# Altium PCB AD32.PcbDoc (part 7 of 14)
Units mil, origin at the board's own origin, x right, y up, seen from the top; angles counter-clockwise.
Board outline 7007.87 x 4368.85 mil, 12 copper layers (Top Layer, Int1 (GND), Int2 (AVDD), Int3 (DVDD), Int4 (GND), Int5 (ST), Int6 (SB), Int8 (AGND), Int7 (AVCC), Int9 (VCCA), Int10 (GND), Bottom Layer), stack 60.136 mil thick; 1350 components, 880 nets, 4712 pads, 2835 vias.
Unrouted connection lines stored in the file: 19.
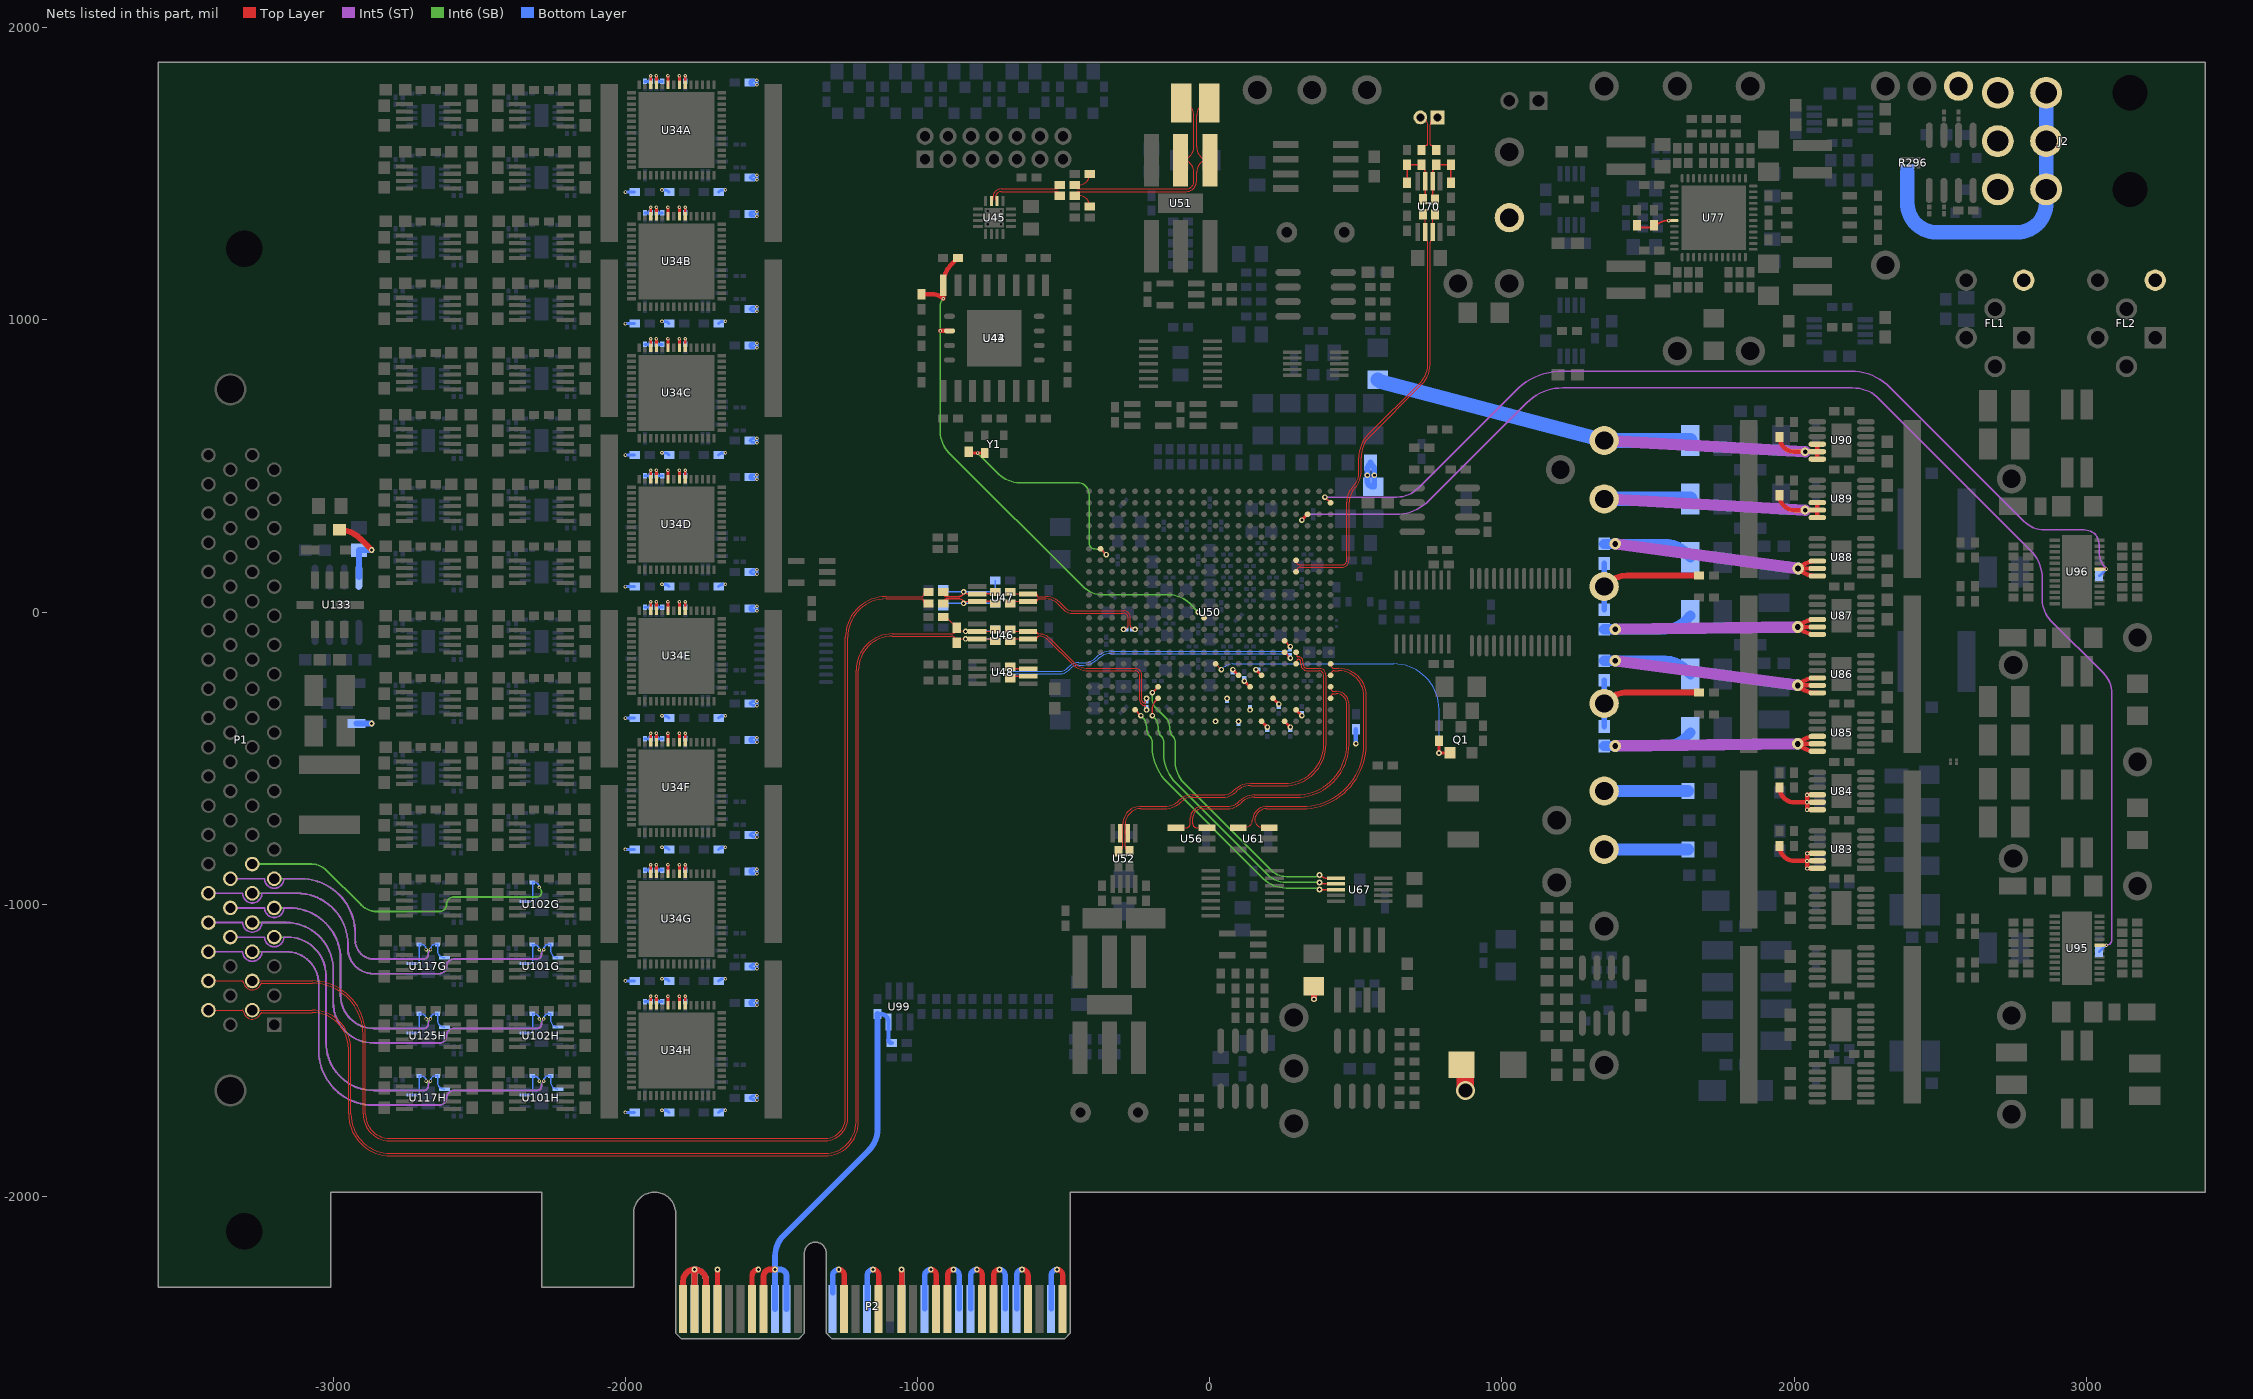
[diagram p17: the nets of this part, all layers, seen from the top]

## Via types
v1: diameter 12, hole 6, Top Layer to Bottom Layer, tented both sides, 1497 vias
v2: diameter 20, hole 10, Top Layer to Bottom Layer, tented both sides, 364 vias
v3: diameter 19, hole 10, Top Layer to Bottom Layer, tented both sides, 347 vias
v4: diameter 14, hole 7, Top Layer to Bottom Layer, tented both sides, 228 vias
v5: diameter 19.68, hole 7.87, Top Layer to Bottom Layer, 225 vias
v6: diameter 19.02, hole 10, Top Layer to Bottom Layer, tented both sides, 85 vias
v7: diameter 20, hole 10, Top Layer to Bottom Layer, 32 vias
v8: diameter 40, hole 20, Top Layer to Bottom Layer, tented both sides, 14 vias
v9: diameter 30, hole 15, Top Layer to Bottom Layer, tented both sides, 12 vias
v10: diameter 25, hole 13, Top Layer to Bottom Layer, 8 vias
v11: diameter 40, hole 20, Top Layer to Bottom Layer, 6 vias
v12: diameter 50, hole 20, Top Layer to Bottom Layer, 6 vias
v13: diameter 66, hole 47, Top Layer to Bottom Layer, tented both sides, 3 vias
v14: diameter 63, hole 45, Top Layer to Bottom Layer, 2 vias
v15: diameter 50, hole 25, Top Layer to Bottom Layer, 2 vias
v16: diameter 12, hole 6, Top Layer to Bottom Layer, 2 vias
v17: diameter 60, hole 40, Top Layer to Bottom Layer, tented both sides, 1 vias
v18: diameter 60, hole 40, Top Layer to Bottom Layer, 1 vias

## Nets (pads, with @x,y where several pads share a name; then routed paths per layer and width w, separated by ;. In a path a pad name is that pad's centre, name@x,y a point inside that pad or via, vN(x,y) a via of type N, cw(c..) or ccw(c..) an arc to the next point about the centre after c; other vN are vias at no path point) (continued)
ANALOG4.A2_P: P1.23 R569G.2 U102G.3 | length 1230.2
  Int6 (SB) w6: P1.23@-3277.3,-862.5 -3074.1,-862.5 cw(c-3074.1,-933.71) -3023.74,-883.36 -2904.8,-1002.3 ccw(c-2850,-947.5) -2850,-1025 -2637.37,-1025 ccw(c-2637.37,-1000.13) -2612.5,-1000.13 -2612.5,-1000 cw(c-2587.5,-1000) -2587.5,-975 -2302.5,-975 ccw(c-2302.5,-960) -2287.5,-960 ccw(c-2311.64,-960) -2294.57,-942.93 v1(-2295,-942.5)
  Bottom Layer w5: U102G.3@-2343.6,-990.16 -2326.41,-990.16 ccw(c-2326.41,-981.25) -2317.5,-981.25 -2317.5,-926.81 ccw(c-2319.31,-926.81) R569G.2@-2319.31,-925 -2312.5,-925 cw(c-2312.5,-942.5) v1(-2295,-942.5)
ANALOG4.A3_N: P1.22 R617G.1 U117G.5 | length 1003.8
  Int5 (ST) w6: P1.22@-3352.3,-912.5 -3235.3,-912.5 ccw(c-3202.3,-912.5) -3169.3,-912.5 -3159.09,-912.5 -3112.33,-912.5 cw(c-3112.33,-1099.83) -2925,-1099.83 -2925,-1123.44 ccw(c-2860.94,-1123.44) -2860.94,-1187.5 -2690,-1187.5 ccw(c-2690,-1172.5) -2675,-1172.5 cw(c-2650.86,-1172.5) -2667.93,-1155.43 v1(-2667.5,-1155)
  Bottom Layer w5: v1(-2667.5,-1155) cw(c-2650,-1155) -2650,-1137.5 R617G.1@-2643.19,-1137.5 -2643.19,-1158.68 ccw(c-2618.89,-1158.68) U117G.5@-2618.89,-1182.97
ANALOG4.A3_P: P1.21 R633G.2 U117G.3 | length 844.8
  Int6 (SB) w6: P1.21@-3202.3,-912.5 -3112.33,-912.5 cw(c-3112.33,-1099.83) -2925,-1099.83 -2925,-1123.44 ccw(c-2860.94,-1123.44) -2860.94,-1187.5 -2690,-1187.5 ccw(c-2690,-1172.5) -2675,-1172.5 ccw(c-2699.14,-1172.5) -2682.07,-1155.43 v1(-2682.5,-1155)
  Bottom Layer w5: U117G.3@-2731.1,-1202.66 -2713.91,-1202.66 ccw(c-2713.91,-1193.75) -2705,-1193.75 -2705,-1141.88 ccw(c-2711.19,-1141.88) R633G.2@-2706.81,-1137.5 -2700,-1137.5 cw(c-2700,-1155) v1(-2682.5,-1155)
ANALOG4.A4_N: P1.20 R553G.1 U101G.5 | length 1490.4
  Int5 (ST) w6: P1.20@-3427.3,-962.5 -3310.3,-962.5 ccw(c-3277.3,-962.5) -3244.3,-962.5 -3124.63,-962.5 cw(c-3124.63,-1137.13) -2950,-1137.13 -2950,-1150.27 ccw(c-2862.77,-1150.27) -2862.77,-1237.5 -2637.5,-1237.5 ccw(c-2637.5,-1212.5) -2612.5,-1212.5 cw(c-2587.5,-1212.5) -2587.5,-1187.5 -2302.5,-1187.5 ccw(c-2302.5,-1172.5) -2287.5,-1172.5 cw(c-2263.36,-1172.5) -2280.43,-1155.43 v1(-2280,-1155)
  Bottom Layer w5: v1(-2280,-1155) cw(c-2262.5,-1155) -2262.5,-1137.5 R553G.1@-2255.69,-1137.5 -2255.69,-1158.68 ccw(c-2231.39,-1158.68) U101G.5@-2231.39,-1182.97
ANALOG4.A4_P: P1.19 R577G.2 U101G.3 | length 1329
  Int6 (SB) w6: P1.19@-3277.3,-962.5 -3124.63,-962.5 cw(c-3124.63,-1137.13) -2950,-1137.13 -2950,-1150.27 ccw(c-2862.77,-1150.27) -2862.77,-1237.5 -2637.5,-1237.5 ccw(c-2637.5,-1212.5) -2612.5,-1212.5 cw(c-2587.5,-1212.5) -2587.5,-1187.5 -2302.5,-1187.5 ccw(c-2302.5,-1172.5) -2287.5,-1172.5 ccw(c-2311.64,-1172.5) -2294.57,-1155.43 v1(-2295,-1155)
  Bottom Layer w5: U101G.3@-2343.6,-1202.66 -2326.41,-1202.66 ccw(c-2326.41,-1193.75) -2317.5,-1193.75 R577G.2@-2317.5,-1139.41 ; R577G.2@-2319.41,-1137.5 cw(c-2319.41,-1139.41) R577G.2@-2317.5,-1139.41 ; v1(-2295,-1155) ccw(c-2310.59,-1155) -2310.59,-1139.41 R577G.2@-2317.5,-1139.41
ANALOG4.A5_N: P1.18 R618H.1 U125H.5 | length 1123.5
  Int5 (ST) w6: P1.18@-3352.3,-1012.5 -3235.3,-1012.5 ccw(c-3202.3,-1012.5) -3169.3,-1012.5 ; -3167.5,-1012.5 -3151.36,-1012.5 cw(c-3151.36,-1188.86) -2975,-1188.86 -2975,-1312.26 ccw(c-2862.26,-1312.26) -2862.26,-1425 -2690,-1425 ccw(c-2690,-1410) -2675,-1410 cw(c-2650.86,-1410) -2667.93,-1392.93 v1(-2667.5,-1392.5)
  Bottom Layer w5: v1(-2667.5,-1392.5) cw(c-2650,-1392.5) -2650,-1375 R618H.1@-2643.19,-1375 -2643.19,-1396.31 ccw(c-2618.89,-1396.31) U125H.5@-2618.89,-1420.6
ANALOG4.A5_P: P1.17 R634H.2 U125H.3 | length 966.7
  Int6 (SB) w6: P1.17@-3202.3,-1012.5 -3151.36,-1012.5 cw(c-3151.36,-1188.86) -2975,-1188.86 -2975,-1312.26 ccw(c-2862.26,-1312.26) -2862.26,-1425 -2690,-1425 ccw(c-2690,-1410) -2675,-1410 ccw(c-2699.14,-1410) -2682.07,-1392.93 v1(-2682.5,-1392.5)
  Bottom Layer w5: U125H.3@-2731.1,-1440.28 -2714.03,-1440.28 ccw(c-2714.03,-1431.25) -2705,-1431.25 -2705,-1376.81 ccw(c-2706.81,-1376.81) R634H.2@-2706.81,-1375 -2700,-1375 cw(c-2700,-1392.5) v1(-2682.5,-1392.5)
ANALOG4.A6_N: P1.16 R554H.1 U102H.5 | length 1611.6
  Int5 (ST) w6: P1.16@-3427.3,-1062.5 -3310.3,-1062.5 ccw(c-3277.3,-1062.5) -3244.3,-1062.5 -3174.68,-1062.5 cw(c-3163.29,-1225.39) -3000,-1225.39 ; -3000,-1225.03 -3000,-1225.39 ; v1(-2280,-1392.5) -2280.43,-1392.93 ccw(c-2263.36,-1410) -2287.5,-1410 cw(c-2302.5,-1410) -2302.5,-1425 -2587.5,-1425 ccw(c-2587.5,-1450) -2612.5,-1450 cw(c-2637.5,-1450) -2637.5,-1475 -2861.78,-1475 cw(c-2861.78,-1336.78) -3000,-1336.78 -3000,-1225.39
  Bottom Layer w5: v1(-2280,-1392.5) cw(c-2262.5,-1392.5) -2262.5,-1375 R554H.1@-2255.69,-1375 -2255.69,-1396.18 ccw(c-2231.39,-1396.18) U102H.5@-2231.39,-1420.47
ANALOG4.A6_P: P1.15 R569H.2 U102H.3 | length 1453.2
  Int6 (SB) w6: P1.15@-3277.3,-1062.5 -3162.53,-1062.5 cw(c-3162.53,-1225.03) -3000,-1225.03 ; -3000,-1225.3 -3000,-1336.78 ccw(c-2861.78,-1336.78) -2862.5,-1475 ; v1(-2295,-1392.5) -2294.57,-1392.93 cw(c-2311.64,-1410) -2287.5,-1410 cw(c-2302.5,-1410) -2302.5,-1425 -2587.5,-1425 ccw(c-2587.5,-1450) -2612.5,-1450 -2612.5,-1450.13 cw(c-2637.37,-1450.13) -2637.37,-1475 -2861.78,-1475 ; -2862.5,-1475 ccw(c-2861.78,-1336.78) -2861.78,-1475 ; -2862.5,-1475 -2861.78,-1475
  Bottom Layer w5: U102H.3@-2343.6,-1440.16 -2326.41,-1440.16 ccw(c-2326.41,-1431.25) -2317.5,-1431.25 -2317.5,-1376.81 ccw(c-2319.31,-1376.81) R569H.2@-2319.31,-1375 -2312.5,-1375 cw(c-2312.5,-1392.5) v1(-2295,-1392.5)
ANALOG4.A7_N: P1.14 R617H.1 U117H.5 | length 1235.1
  Int5 (ST) w6: P1.14@-3352.3,-1112.5 -3235.3,-1112.5 ccw(c-3202.3,-1112.5) -3169.3,-1112.5 -3156.11,-1112.5 cw(c-3156.11,-1243.61) -3025,-1243.61 -3025,-1473.44 ccw(c-2860.94,-1473.44) -2860.94,-1637.5 -2690,-1637.5 ccw(c-2690,-1622.5) -2675,-1622.5 cw(c-2650.86,-1622.5) -2667.93,-1605.43 v1(-2667.5,-1605)
  Bottom Layer w5: v1(-2667.5,-1605) cw(c-2650,-1605) -2650,-1587.5 R617H.1@-2643.19,-1587.5 -2643.19,-1608.68 ccw(c-2618.89,-1608.68) U117H.5@-2618.89,-1632.97
ANALOG4.A7_P: P1.13 R633H.2 U117H.3 | length 1075.6
  Int6 (SB) w6: P1.13@-3202.3,-1112.5 -3156.97,-1112.5 cw(c-3156.97,-1244.47) -3025,-1244.47 -3025,-1473.44 ccw(c-2860.94,-1473.44) -2860.94,-1637.5 -2690,-1637.5 ccw(c-2690,-1622.5) -2675,-1622.5 ccw(c-2699.14,-1622.5) -2682.07,-1605.43 v1(-2682.5,-1605)
  Bottom Layer w5: U117H.3@-2731.1,-1652.66 -2713.91,-1652.66 ccw(c-2713.91,-1643.75) -2705,-1643.75 -2705,-1591.88 ccw(c-2711.19,-1591.88) R633H.2@-2706.81,-1587.5 -2700,-1587.5 cw(c-2700,-1605) v1(-2682.5,-1605)
ANALOG4.A8_N: P1.12 R553H.1 U101H.5 | length 1725.2
  Int5 (ST) w6: P1.12@-3427.3,-1162.5 -3310.3,-1162.5 ccw(c-3277.3,-1162.5) -3244.3,-1162.5 -3160.02,-1162.5 cw(c-3160.02,-1272.52) -3050,-1272.52 -3050,-1500.27 ccw(c-2862.77,-1500.27) -2862.77,-1687.5 -2637.5,-1687.5 ccw(c-2637.5,-1662.5) -2612.5,-1662.5 cw(c-2587.5,-1662.5) -2587.5,-1637.5 -2302.5,-1637.5 ccw(c-2302.5,-1622.5) -2287.5,-1622.5 cw(c-2263.36,-1622.5) -2280.43,-1605.43 v1(-2280,-1605)
  Bottom Layer w5: v1(-2280,-1605) cw(c-2262.5,-1605) -2262.5,-1587.5 R553H.1@-2255.69,-1587.5 -2255.69,-1608.68 ccw(c-2231.39,-1608.68) U101H.5@-2231.39,-1632.97
ANALOG4.A8_P: P1.11 R577H.2 U101H.3 | length 1563.7
  Int6 (SB) w6: P1.11@-3277.3,-1162.5 -3160.3,-1162.5 cw(c-3160.3,-1272.8) -3050,-1272.8 -3050,-1500.27 ccw(c-2862.77,-1500.27) -2862.77,-1687.5 -2637.5,-1687.5 ccw(c-2637.5,-1662.5) -2612.5,-1662.5 cw(c-2587.5,-1662.5) -2587.5,-1637.5 -2302.5,-1637.5 ccw(c-2302.5,-1622.5) -2287.5,-1622.5 ccw(c-2311.64,-1622.5) -2294.57,-1605.43 v1(-2295,-1605)
  Bottom Layer w5: U101H.3@-2343.6,-1652.66 -2326.41,-1652.66 ccw(c-2326.41,-1643.75) -2317.5,-1643.75 R577H.2@-2317.5,-1589.41 ; R577H.2@-2319.41,-1587.5 cw(c-2319.41,-1589.41) R577H.2@-2317.5,-1589.41 ; v1(-2295,-1605) ccw(c-2310.59,-1605) -2310.59,-1589.41 R577H.2@-2317.5,-1589.41
APWR1.SYNC_DIFF: R293.1 U50.Y3 U95.19 | length 4438.9
  Top Layer w9: U95.19@3045.25,-1140.16 v1(3068.75,-1140.16)
  Top Layer w10: v3(314.96,314.96) U50.Y3@334.65,334.65
  Int5 (ST) w5: v3(314.96,314.96) 320.73,320.73 cw(c354.33,287.12) 354.33,334.65 637.02,334.65 ccw(c637.02,493.7) 749.49,381.23 1084.36,716.1 cw(c1208.44,592.02) 1208.44,767.5 2199.65,767.5 cw(c2199.65,637.26) 2291.75,729.35 2808.78,212.32 cw(c2710.71,114.25) 2849.4,114.25 2849.4,41.8 ccw(c2949.4,41.8) 2878.69,-28.91 3058.21,-208.43 cw(c2987.5,-279.14) 3087.5,-279.14 3087.5,-1121.41 cw(c3068.75,-1121.41) v1(3068.75,-1140.16)
  Bottom Layer w9: R293.1@3043.75,-1163.09 3065.22,-1141.62 cw(c3068.75,-1145.15) v1(3068.75,-1140.16)
APWR2.SYNC_DUAL: R294.1 U50.AA1 U96.19 | length 3231.7
  Top Layer w6: v3(393.7,393.7) U50.AA1@413.39,374.02
  Top Layer w9: U96.19@3045.25,147.34 v1(3068.75,147.34)
  Int5 (ST) w5: v3(393.7,393.7) 640.48,393.7 ccw(c640.48,493.7) 711.19,422.99 1044.81,756.61 cw(c1208.92,592.5) 1208.92,824.59 2195.14,824.59 cw(c2195.14,637.42) 2327.49,769.77 2786.71,310.54 ccw(c2857.43,381.25) 2857.43,281.25 2993.75,281.25 cw(c2993.75,231.25) 3043.75,231.25 3043.75,207.7 ccw(c3129.11,207.7) v1(3068.75,147.34)
  Bottom Layer w9: R294.1@3043.75,124.41 ccw(c3043.75,129.4) R294.1@3047.27,125.87 ; R294.1@3047.28,125.87 v1(3068.75,147.34)
AVCC: C137.1 C178.1 C188.1 C202.1 C207.2 C217.2 R235.2 TP19.1 U50.D6 U50.D10 U50.E8 U50.F7 U50.F9 U84.10 U84.11 U84.12 | length 677.2
  Top Layer w10: v3(78.74,-196.85) U50.F9@98.43,-216.54 ; v3(118.11,-236.22) U50.E8@137.8,-255.91 ; v3(157.48,-196.85) U50.F7@177.17,-216.54 ; U50.D6@216.54,-295.28 v3(236.22,-314.96)
  Top Layer w16: R235.2@1950,-600.59 ccw(c2000.3,-600.59) 2000.3,-650.89 v4(2044.47,-650.89) ; U84.12@2079.44,-676.48 v4(2044.47,-676.48) v4(2044.47,-650.89) ; U84.11@2079.44,-650.89 v4(2044.47,-650.89) ; U84.10@2079.44,-625.3 v4(2044.47,-625.3) v4(2044.47,-650.89)
  Bottom Layer w40: TP19.1@1350,-612.5 C137.1@1636.61,-612.5
  other v3: 59.06,-295.28
AVCC1V8: C64.2 C155.1 FR9.1 R215.2 TP11.1 U77.7 | length 322.7
  Top Layer w7: C64.2@1462.5,1324.41 ccw(c1481.51,1343.42) 1481.51,1316.54 1520,1316.54 1524.26,1320.8 cw(c1571,1274.06) v1(1571,1340.16)
  Top Layer w10: v1(1571,1340.16) U77.7@1590.16,1340.16
  Bottom Layer w20: FR9.1@539.37,448.82 ccw(c559.06,448.82) FR9.1@559.06,429.13 ccw(c559.06,433.07) 562.99,433.07 562.99,474.65 ccw(c542.99,474.58) 562.99,474.74 562.83,494.25 C155.1@550.2,511.81 546.68,506.11 539.37,494.25 v3(539.37,468.5) FR9.1@539.37,448.82
  other v3: 562.99,468.5
AVCOCLK2_N: C6.1 U45.7 | length 269.7
  Top Layer w4: U45.7@-747.34,1406.5 ccw(c-747.34,1411.84) -742,1411.84 -742,1420 cw(c-713.75,1420) -713.75,1448.25 -527.34,1448.25 ccw(c-527.34,1462.5) C6.1@-513.09,1462.5
AVCOCLK2_P: C4.1 U45.6 | length 255.6
  Top Layer w4: U45.6@-727.66,1406.5 cw(c-727.66,1411.84) -733,1411.84 -733,1420 cw(c-713.75,1420) -713.75,1439.25 -527.34,1439.25 cw(c-527.34,1425) C4.1@-513.09,1425
AVCOCLK_N: C6.2 R7.1 TP1.1 U51.5 | length 849.6
  Top Layer w4: R7.1@-410.66,1500 cw(c-448.16,1500) -448.16,1462.5 C6.2@-461.91,1462.5 ccw(c-447.66,1462.5) -447.66,1448.25 -81.25,1448.25 ccw(c-81.25,1475) -54.5,1475 -54.5,1506.25 ccw(c-94.99,1506.25) -94.99,1546.74 U51.5@-100,1546.74 ccw(c-100,1592.24) -54.5,1592.24 -54.5,1699.5 ccw(c-97.5,1699.5) TP1.1@-97.5,1742.5
AVCOCLK_P: C4.2 R5.2 TP2.1 U51.4 | length 863.7
  Top Layer w4: R5.2@-410.66,1387.5 ccw(c-448.16,1387.5) -448.16,1425 C4.2@-461.91,1425 cw(c-447.66,1425) -447.66,1439.25 -81.25,1439.25 ccw(c-81.25,1475) -45.5,1475 -45.5,1506.25 cw(c-5.01,1506.25) -5.01,1546.74 U51.4@0,1546.74 cw(c0,1592.24) -45.5,1592.24 -45.5,1699.5 cw(c-2.5,1699.5) TP2.1@-2.5,1742.5
AVDD1V8: C289A.1 C289B.1 C289C.1 C289D.1 C289E.1 C289F.1 C289G.1 C289H.1 R223.1 R350.2 R351.1 TP21.1 U34A.21 U34B.21 U34C.21 U34D.21 U34E.21 U34F.21 U34G.21 U34H.21 | length 1378.2
  Top Layer w10: U34H.21@-1815.16,-1345.38 v1(-1815.16,-1314.57) ; U34G.21@-1815.16,-895.38 v1(-1815.16,-864.57) ; U34F.21@-1815.16,-445.38 v1(-1815.16,-414.57) ; U34E.21@-1815.16,4.62 v1(-1815.16,35.43) ; U34D.21@-1815.16,454.62 v1(-1815.16,485.43) ; U34C.21@-1815.16,904.62 v1(-1815.16,935.43) ; U34B.21@-1815.16,1354.62 v1(-1815.16,1385.43) ; U34A.21@-1815.16,1804.62 v1(-1815.16,1835.43)
  Top Layer w20: TP21.1@1350,87.5 1358.21,95.71 cw(c1428.92,25) 1428.92,125 R223.1@1674.41,125
  Bottom Layer w10: C289H.1@-1567.04,-1337.5 C289H.1@-1574.41,-1337.5 ; C289G.1@-1567.04,-887.5 C289G.1@-1574.41,-887.5 ; C289F.1@-1567.04,-437.5 C289F.1@-1574.41,-437.5 ; C289E.1@-1567.04,12.5 C289E.1@-1574.41,12.5 ; C289D.1@-1567.04,462.5 C289D.1@-1574.41,462.5 ; C289C.1@-1567.04,912.5 C289C.1@-1574.41,912.5 ; C289B.1@-1567.04,1362.5 C289B.1@-1574.41,1362.5 ; C289A.1@-1567.04,1812.5 C289A.1@-1574.41,1812.5 ; C289H.1@-1574.41,-1337.5 cw(c-1566.91,-1337.5) -1566.91,-1330 v1(-1550,-1330) v1(-1550,-1345) -1566.91,-1345 cw(c-1566.91,-1337.5) C289H.1@-1574.41,-1337.5 ; C289G.1@-1574.41,-887.5 cw(c-1566.91,-887.5) -1566.91,-880 v1(-1550,-880) v1(-1550,-895) -1566.91,-895 cw(c-1566.91,-887.5) C289G.1@-1574.41,-887.5 ; C289F.1@-1574.41,-437.5 cw(c-1566.91,-437.5) -1566.91,-430 v1(-1550,-430) v1(-1550,-445) -1566.91,-445 cw(c-1566.91,-437.5) C289F.1@-1574.41,-437.5 ; C289E.1@-1574.41,12.5 ccw(c-1566.91,12.5) -1566.91,5 v1(-1550,5) v1(-1550,20) -1566.91,20 ccw(c-1566.91,12.5) C289E.1@-1574.41,12.5 ; C289D.1@-1574.41,462.5 cw(c-1566.91,462.5) -1566.91,470 v1(-1550,470) v1(-1550,455) -1566.91,455 cw(c-1566.91,462.5) C289D.1@-1574.41,462.5 ; C289C.1@-1574.41,912.5 ccw(c-1566.91,912.5) -1566.91,905 v1(-1550,905) v1(-1550,920) -1566.91,920 ccw(c-1566.91,912.5) C289C.1@-1574.41,912.5 ; C289B.1@-1574.41,1362.5 ccw(c-1566.91,1362.5) -1566.91,1355 v1(-1550,1355) v1(-1550,1370) -1566.91,1370 ccw(c-1566.91,1362.5) C289B.1@-1574.41,1362.5 ; C289A.1@-1574.41,1812.5 ccw(c-1566.91,1812.5) -1566.91,1805 v1(-1550,1805) v1(-1550,1820) -1566.91,1820 ccw(c-1566.91,1812.5) C289A.1@-1574.41,1812.5
  Bottom Layer w20: R350.2@1350,8.46 TP21.1@1350,87.5 R351.1@1350,166.54
AVDD5V0: C134.2 C288A.1 C288B.1 C288C.1 C288D.1 C288E.1 C288F.1 C288G.1 C288H.1 C352A.1 C352B.1 C352C.1 C352D.1 C352E.1 C352F.1 C352G.1 C352H.1 C361A.1 C361B.1 C361C.1 C361D.1 C361E.1 C361F.1 C361G.1 C361H.1 C512.1 D2.2 R2.2 R318.1 TP22.1 U34A.26 U34B.26 U34C.26 U34D.26 U34E.26 U34F.26 U34G.26 U34H.26 U89.10 U89.11 U89.12 U133.8 | length 2613
  Top Layer w10: U34H.26@-1913.58,-1345.38 v1(-1913.58,-1314.57) ; U34G.26@-1913.58,-895.38 v1(-1913.58,-864.57) ; U34F.26@-1913.58,-445.38 v1(-1913.58,-414.57) ; U34E.26@-1913.58,4.62 v1(-1913.58,35.43) ; U34D.26@-1913.58,454.62 v1(-1913.58,485.43) ; U34C.26@-1913.58,904.62 v1(-1913.58,935.43) ; U34B.26@-1913.58,1354.62 v1(-1913.58,1385.43) ; U34A.26@-1913.58,1804.62 v1(-1913.58,1835.43)
  Top Layer w15: R318.1@1950,399.41 ccw(c2000.3,399.41) 2000.3,349.11 v9(2037.5,349.11) U89.11@2079.44,349.11 ; U89.12@2079.44,323.52 U89.11@2079.44,349.11 ; U89.10@2079.44,374.7 U89.11@2079.44,349.11
  Top Layer w20: R2.2@-2979.04,281.25 -2978.92,281.25 cw(c-2978.92,181.25) -2908.21,251.96 v3(-2868.75,212.5)
  Int5 (ST) w40: TP22.1@1350,387.5 v9(2037.5,349.11)
  Bottom Layer w10: C361H.1@-1933.27,-1333.44 C352H.1@-1913.58,-1333.44 v1(-1913.58,-1314.57) ; C361G.1@-1933.27,-883.44 C352G.1@-1913.58,-883.44 v1(-1913.58,-864.57) ; C361F.1@-1933.27,-433.44 C352F.1@-1913.58,-433.44 v1(-1913.58,-414.57) ; C361E.1@-1933.27,16.56 C352E.1@-1913.58,16.56 v1(-1913.58,35.43) ; C361D.1@-1933.27,466.56 C352D.1@-1913.58,466.56 v1(-1913.58,485.43) ; C361C.1@-1933.27,916.56 C352C.1@-1913.58,916.56 v1(-1913.58,935.43) ; C361B.1@-1933.27,1366.56 C352B.1@-1913.58,1366.56 v1(-1913.58,1385.43) ; C361A.1@-1933.27,1816.56 C352A.1@-1913.58,1816.56 v1(-1913.58,1835.43) ; C288H.1@-1574.41,-1662.5 cw(c-1556.3,-1680.61) -1556.3,-1655 v1(-1550,-1655) v1(-1550,-1670) -1556.3,-1670 cw(c-1556.3,-1644.39) C288H.1@-1574.41,-1662.5 ; C288G.1@-1574.41,-1212.5 cw(c-1556.3,-1230.61) -1556.3,-1205 v1(-1550,-1205) v1(-1550,-1220) -1556.3,-1220 cw(c-1556.3,-1194.39) C288G.1@-1574.41,-1212.5 ; C288F.1@-1574.41,-762.5 cw(c-1556.3,-780.61) -1556.3,-755 v1(-1550,-755) v1(-1550,-770) -1556.3,-770 cw(c-1556.3,-744.39) C288F.1@-1574.41,-762.5 ; C288E.1@-1574.41,-312.5 ccw(c-1556.3,-294.39) -1556.3,-320 v1(-1550,-320) v1(-1550,-305) -1556.3,-305 ccw(c-1556.3,-330.61) C288E.1@-1574.41,-312.5 ; C288D.1@-1574.41,137.5 cw(c-1556.3,119.39) -1556.3,145 v1(-1550,145) v1(-1550,130) -1556.3,130 cw(c-1556.3,155.61) C288D.1@-1574.41,137.5 ; C288C.1@-1574.41,587.5 ccw(c-1556.3,605.61) -1556.3,580 v1(-1550,580) v1(-1550,595) -1556.3,595 ccw(c-1556.3,569.39) C288C.1@-1574.41,587.5 ; C288B.1@-1574.41,1037.5 cw(c-1556.3,1019.39) -1556.3,1045 v1(-1550,1045) v1(-1550,1030) -1556.3,1030 cw(c-1556.3,1055.61) C288B.1@-1574.41,1037.5 ; C288A.1@-1574.41,1487.5 cw(c-1556.3,1469.39) -1556.3,1495 v1(-1550,1495) v1(-1550,1480) -1556.3,1480 cw(c-1556.3,1505.61) C288A.1@-1574.41,1487.5
  Bottom Layer w20: D2.2@-2920.57,-381.25 v3(-2868.75,-381.25) ; U133.8@-2912.5,119.49 C512.1@-2912.5,211.61 cw(c-2911.61,211.61) -2911.61,212.5 v3(-2868.75,212.5)
  Bottom Layer w50: TP22.1@1350,387.5 C134.2@1644.88,387.5
AVDDL1V8: C132.2 R350.1 U87.10 U87.11 U87.12 | length 1149.2
  Top Layer w15: U87.12@2079.44,-76.48 2074.28,-76.48 cw(c2074.28,10.9) v8(2012.5,-50.89) ; U87.11@2079.44,-50.89 v8(2012.5,-50.89) ; U87.10@2079.44,-25.3 2074.28,-25.3 ccw(c2074.28,-112.67) v8(2012.5,-50.89)
  Int5 (ST) w40: v8(1387.5,-58.46) v8(2012.5,-50.89)
  Bottom Layer w35: R350.1@1350,-58.46 v8(1387.5,-58.46) 1557.5,-58.46 ccw(c1557.5,41.54) 1628.21,-29.18 C132.2@1644.88,-12.5
AVDDR1V8: C133.2 R351.2 U88.10 U88.11 U88.12 | length 1152.2
  Top Layer w15: U88.12@2079.44,123.52 2075.56,123.52 cw(c2075.56,210.9) v8(2013.78,149.11) ; U88.11@2079.44,149.11 v8(2013.78,149.11) ; U88.10@2079.44,174.7 2075.56,174.7 ccw(c2075.56,87.33) v8(2013.78,149.11)
  Int5 (ST) w40: v8(1387.5,233.46) v8(2013.78,149.11)
  Bottom Layer w35: R351.2@1350,233.46 v8(1387.5,233.46) 1557.5,233.46 cw(c1557.5,133.46) 1628.21,204.18 C133.2@1644.88,187.5
AVTT: C136.2 C172.1 C175.2 C184.1 C200.2 C206.2 R234.2 R357.2 TP18.1 U50.B5 U50.B7 U50.B9 U50.B11 U50.C4 U50.C8 U83.10 U83.11 U83.12 | length 769.5
  Top Layer w10: U50.B7@177.17,-374.02 v3(196.85,-393.7) ; U50.B5@255.91,-374.02 v3(275.59,-393.7) ; U50.C4@295.28,-334.65 v3(314.96,-354.33) ; v4@2044.81,-851.22 v4(2044.47,-851.56) 2044.47,-850.89 v4@2044.83,-850.89 ; v4(2044.83,-877.15) 2044.83,-876.48 U83.12@2079.44,-876.48 ; v4@2044.83,-851.22 2079.1,-851.22 U83.11@2079.44,-850.89
  Top Layer w16: R234.2@1950,-800.59 ccw(c2000.97,-800.59) 2000.97,-851.56 v4(2044.47,-851.56) ; v4(2044.83,-877.15) 2045.15,-876.84 2079.07,-876.84 U83.12@2079.44,-876.48 ; v4@2044.83,-876.48 2044.83,-851.22 v4@2044.83,-850.89 ; U83.11@2079.44,-850.89 v4@2044.83,-850.89 ; U83.10@2079.44,-825.3 2079.07,-825.66 2045.15,-825.66 v4(2044.83,-825.97) v4@2044.83,-850.89
  Bottom Layer w16: v3(500,-450) R357.2@500,-400.59
  Bottom Layer w40: TP18.1@1350,-812.5 C136.2@1636.61,-812.5
  other v3: 19.69,-374.02 98.43,-374.02 137.8,-334.65
BUS3.3V: C287.1 P2.A9 P2.A10 P2.B8 R397.2 U99.6 | length 1606.9
  Top Layer w20: P2.B8@-1527.17,-2385 -1527.17,-2272.93 cw(c-1504.23,-2272.93) -1504.23,-2250 v2(-1487.8,-2250)
  Bottom Layer w15: C287.1@-1137.5,-1375.59 -1127.46,-1375.59 cw(c-1127.46,-1403.15) U99.6@-1099.9,-1403.15 -1099.9,-1463.19 ccw(c-1088.09,-1463.19) R397.2@-1088.09,-1475
  Bottom Layer w20: P2.A9@-1487.8,-2385 v2(-1487.8,-2250) ; P2.A10@-1448.43,-2385 -1448.43,-2272.77 ccw(c-1471.19,-2272.77) -1471.19,-2250 v2(-1487.8,-2250) ; C287.1@-1137.5,-1375.59 -1137.5,-1771.08 cw(c-1237.5,-1771.08) -1166.79,-1841.79 -1458.51,-2133.51 ccw(c-1387.8,-2204.22) -1487.8,-2204.22 v2(-1487.8,-2250)
BUS12V: D4.1 P2.A2 P2.A3 P2.B1 P2.B2 P2.B3 | length 835.5
  Top Layer w20: P2.B1@-1802.76,-2385 -1802.76,-2289.37 cw(c-1763.39,-2289.37) v2(-1763.39,-2250) ; P2.B2@-1763.39,-2385 v2(-1763.39,-2250) ; P2.B3@-1724.02,-2385 -1724.02,-2289.37 ccw(c-1763.39,-2289.37) v2(-1763.39,-2250)
  Top Layer w60: D4.1@861.42,-1550 875,-1563.58 v13(875,-1637.5)
  Bottom Layer w20: P2.A2@-1763.39,-2385 v2(-1763.39,-2250) cw(c-1763.39,-2289.37) -1724.02,-2289.37 P2.A3@-1724.02,-2385
CAUX_N: C56.2 R184.2 R185.1 R188.1 U70.3 | length 234.1
  Top Layer w5: R184.2@675,1469.34 R185.1@675,1530.66 C56.2@725,1530.66 cw(c695.54,1501.19) 737.2,1501.19 U70.3@737.2,1474.31 737.2,1430.48 cw(c712.61,1430.48) R188.1@730,1413.09
CAUX_P: C60.2 R190.1 R193.1 R194.2 U70.2 | length 235.3
  Top Layer w5: R190.1@770,1411.84 cw(c787.39,1429.23) 762.8,1429.23 U70.2@762.8,1474.31 762.8,1501.19 cw(c804.46,1501.19) C60.2@775,1530.66 R194.2@825,1530.66 R193.1@825,1469.34
CCLK: R135.1 R142.2 U43.16 U44.6 U50.L12 | length 1903.4
  Top Layer w5: v3(-39.37,0) U50.L12@-19.68,-19.68
  Top Layer w15: R135.1@-987.5,1088.09 -950.14,1088.09 cw(c-950.14,1034.86) v1(-912.5,1072.5) U43.16@-912.5,1118.6 -912.5,1120.49 cw(c-812.5,1120.49) -883.21,1191.2 R142.2@-861.91,1212.5 ; v1(-922.5,962.5) U44.6@-891.04,962.5
  Int6 (SB) w5: v1(-912.5,1072.5) ccw(c-888.36,1048.36) -922.5,1048.36 v1(-922.5,962.5) -922.5,616.87 ccw(c-822.5,616.87) -893.21,546.16 -435.39,88.34 ccw(c-364.68,159.06) -364.68,59.06 -139.85,59.06 cw(c-139.85,-40.94) -69.14,29.77 v3(-39.37,0)
CLK_AUX_N: C56.1 J1.2 | length 137.3
  Top Layer w4: J1.2@720.47,1693.26 cw(c720.47,1667.73) 746,1667.73 746,1602.06 cw(c741,1602.06) 744.54,1598.52 cw(c741,1602.06) 741,1597.06 ccw(c741,1585.66) 732.94,1593.72 727.78,1588.56 ccw(c734.5,1581.84) C56.1@725,1581.84
CLK_AUX_P: C60.1 J1.1 | length 137.3
  Top Layer w4: C60.1@775,1581.84 ccw(c765.5,1581.84) 772.22,1588.56 767.06,1593.72 ccw(c759,1585.66) 759,1597.06 cw(c759,1602.06) 755.46,1598.52 cw(c759,1602.06) 754,1602.06 754,1667.73 cw(c779.53,1667.73) J1.1@779.53,1693.26
CLK_E_N: P1.4 R144.2 R150.1 R383.1 U46.3 | length 4893.9
  Top Layer w4: P1.4@-3427.3,-1362.5 -3312.42,-1362.5 cw(c-3312.45,-1367.5) -3307.5,-1366.78 ccw(c-3277.3,-1362.5) -3248.91,-1373.63 cw(c-3244.27,-1375.5) -3244.3,-1370.5 -3072.5,-1370.5 cw(c-3072.5,-1495) -2948,-1495 -2948,-1717.62 ccw(c-2805.12,-1717.62) -2805.12,-1860.5 -1317.5,-1860.5 ccw(c-1317.5,-1745.5) -1202.5,-1745.5 -1202.5,-198.74 cw(c-1086.5,-198.74) -1086.5,-82.74 -884.2,-82.74 cw(c-884.2,-98.3) -868.64,-98.3 ccw(c-860.11,-98.3) R144.2@-866.14,-104.33 -865.64,-103.83 cw(c-835.96,-133.51) v3(-835.96,-91.54) U46.3@-795.47,-91.54 -750.89,-91.54 cw(c-750.89,-115.06) R150.1@-734.25,-98.43
  Bottom Layer w5: v3(-835.96,-91.54) -750.89,-91.54 cw(c-750.89,-115.06) R383.1@-734.25,-98.43
CLK_E_P: P1.3 R138.1 R144.1 R151.1 R385.2 U46.2 | length 4778.3
  Top Layer w4: P1.3@-3277.3,-1362.5 -3072.5,-1362.5 cw(c-3072.5,-1495) -2940,-1495 -2940,-1717.62 ccw(c-2805.12,-1717.62) -2805.12,-1852.5 -1317.5,-1852.5 ccw(c-1317.5,-1745.5) -1210.5,-1745.5 -1210.5,-198.74 cw(c-1086.5,-198.74) -1086.5,-74.74 -884.2,-74.74 ccw(c-884.2,-59.19) -868.64,-59.19 cw(c-860.11,-59.19) R144.1@-866.14,-53.15 -896.7,-22.59 ccw(c-911.89,-37.78) R138.1@-911.89,-16.3 ; R144.1@-865.64,-53.65 ccw(c-835.96,-23.97) v3(-835.96,-65.94) U46.2@-795.47,-65.94 -750.89,-65.94 ccw(c-750.89,-42.42) R151.1@-734.25,-59.06
  Bottom Layer w5: v3(-835.96,-65.94) -750.89,-65.94 ccw(c-750.89,-42.42) R385.2@-734.25,-59.06
CLK_O_N: C35.1 P1.8 | length 4687.4
  Top Layer w4: P1.8@-3427.3,-1262.5 -3312.42,-1262.5 cw(c-3312.45,-1267.5) -3307.5,-1266.78 ccw(c-3277.3,-1262.5) -3248.91,-1273.63 cw(c-3244.27,-1275.5) -3244.3,-1270.5 -3072.5,-1270.5 cw(c-3072.5,-1445) -2898,-1445 -2898,-1717.62 ccw(c-2806.15,-1717.62) -2806.15,-1809.47 -1317.5,-1809.47 ccw(c-1317.5,-1731.47) -1239.5,-1731.47 -1239.5,-86.79 cw(c-1107.5,-86.79) -1107.5,45.21 -983.31,45.21 ccw(c-967.62,45.21) -967.62,29.53 C35.1@-963.09,29.53
CLK_O_P: C36.1 P1.7 | length 4512.4
  Top Layer w4: P1.7@-3277.3,-1262.5 -3072.5,-1262.5 cw(c-3072.5,-1445) -2890,-1445 -2890,-1717.62 ccw(c-2806.15,-1717.62) -2806.15,-1801.47 -1317.5,-1801.47 ccw(c-1317.5,-1731.47) -1247.5,-1731.47 -1247.5,-86.79 cw(c-1107.5,-86.79) -1107.5,53.21 -983.31,53.21 cw(c-967.62,53.21) -967.62,68.9 C36.1@-963.09,68.9
CLKE_N: R150.2 R156.2 U46.6 U50.C17 | length 633.1
  Top Layer w4: R150.2@-683.07,-98.43 cw(c-666.44,-115.06) -666.44,-91.54 U46.6@-622.24,-91.54 -597.04,-91.54 ccw(c-597.04,-82.74) -588.25,-82.74 -584.65,-82.74 cw(c-584.65,-126.86) -553.45,-95.66 -471.6,-177.51 ccw(c-415.4,-121.3) -415.4,-200.79 -256.03,-200.79 cw(c-256.03,-216.54) -240.28,-216.54 -240.28,-302.17 ccw(c-223.5,-302.17) -223.5,-318.96 cw(c-223.5,-323.42) -219.04,-323.42 -219.04,-328.61 ccw(c-210.5,-328.61) v6(-216.54,-334.65)
CLKE_P: R151.2 R156.1 U46.7 U50.D17 | length 633.1
  Top Layer w4: R151.2@-683.07,-59.06 ccw(c-666.44,-42.42) -666.44,-65.94 U46.7@-622.24,-65.94 -597.04,-65.94 cw(c-597.04,-74.74) -588.25,-74.74 -584.65,-74.74 cw(c-584.65,-126.86) -547.79,-90.01 -465.95,-171.85 ccw(c-415.4,-121.3) -415.4,-192.79 -256.03,-192.79 cw(c-256.03,-216.54) -232.28,-216.54 -232.28,-302.17 ccw(c-223.5,-302.17) -223.5,-310.96 ccw(c-223.5,-306.5) -219.04,-306.5 -219.04,-301.31 cw(c-210.5,-301.31) v6(-216.54,-295.28)
CLKM_O_N: C35.2 R152.1 R384.1 R390.2 U47.3 | length 383.3
  Top Layer w5: C35.2@-911.91,29.53 ccw(c-917.94,35.56) -909.41,35.56 cw(c-899.76,35.56) -899.76,45.21 -858.2,45.21 cw(c-858.2,29.53) v3(-842.52,29.53) cw(c-825.89,12.89) -825.89,36.42 U47.3@-795.47,36.42 -750.89,36.42 cw(c-750.89,12.89) R152.1@-734.25,29.53
  Bottom Layer w5: R390.2@-911.89,19.69 cw(c-902.05,19.69) -902.05,29.53 v3(-842.52,29.53) R384.1@-734.25,29.53
CLKM_O_P: C36.2 R153.1 R386.2 R387.2 R391.1 U47.2 | length 422.6
  Top Layer w5: C36.2@-911.91,68.9 cw(c-917.94,62.86) -909.41,62.86 ccw(c-899.76,62.86) -899.76,53.21 -858.2,53.21 ccw(c-858.2,68.9) v3(-842.52,68.9) ccw(c-825.89,85.53) -825.89,62.01 U47.2@-795.47,62.01 -750.89,62.01 ccw(c-750.89,85.53) R153.1@-734.25,68.9
  Bottom Layer w5: R391.1@-911.89,78.74 ccw(c-902.05,78.74) -902.05,68.9 v3(-842.52,68.9) R386.2@-734.25,68.9 R387.2@-734.25,108.27
CLKO_N: R152.2 R157.2 U47.6 U50.K19 | length 484.2
  Top Layer w4: R152.2@-683.07,29.53 cw(c-666.44,12.89) -666.44,36.42 U47.6@-622.24,36.42 -597.04,36.42 ccw(c-597.04,45.21) -588.25,45.21 -560.87,45.21 cw(c-560.87,-12.79) -519.85,28.22 -501.72,10.09 ccw(c-467.85,43.96) -467.85,-3.94 -295.34,-3.94 cw(c-295.34,-19.68) -279.59,-19.68 -279.59,-46.91 cw(c-289.24,-46.91) -289.24,-56.56 ccw(c-289.24,-65.09) v6(-295.28,-59.06)
CLKO_P: R153.2 R157.1 U47.7 U50.K18 | length 496.8
  Top Layer w4: R153.2@-683.07,68.9 ccw(c-666.44,85.53) -666.44,62.01 U47.7@-622.24,62.01 -597.04,62.01 cw(c-597.04,53.21) -588.25,53.21 -560.87,53.21 cw(c-560.87,-12.8) -514.19,33.88 -496.06,15.75 ccw(c-467.85,43.96) -467.85,4.06 -295.34,4.06 cw(c-295.34,-19.68) -271.59,-19.68 -271.59,-46.91 ccw(c-261.94,-46.91) -261.94,-56.56 cw(c-261.94,-65.09) v6(-255.91,-59.06)
CLOCK.ACLK: U50.C18 U67.8 | length 1006
  Top Layer w5: U50.C18@-255.91,-334.65 v6(-236.22,-354.33) ; v2(375,-950) U67.8@431.79,-950
  Int6 (SB) w5: v6(-236.22,-354.33) -230.45,-360.1 cw(c-264.06,-393.7) -216.54,-393.7 -216.54,-399.47 ccw(c-182.93,-399.47) -206.69,-423.23 cw(c-230.45,-446.99) -196.85,-446.99 -196.85,-462.6 ccw(c-29.17,-462.6) -147.74,-581.17 183.63,-912.53 ccw(c261.25,-834.91) 261.25,-944.69 362.17,-944.68 cw(c362.17,-962.83) v2(375,-950)
CLOCK.ACNV: U50.E16 U67.6 | length 1025
  Top Layer w5: v6(-196.85,-275.59) U50.E16@-177.17,-255.91 ; v2(375,-900) ccw(c400.66,-874.34) 400.66,-910.63 U67.6@431.79,-910.63
  Int6 (SB) w5: v6(-196.85,-275.59) -196.85,-295.28 ccw(c-149.33,-295.28) -182.93,-328.88 -151.71,-360.1 cw(c-185.32,-393.7) -137.8,-393.7 -137.8,-399.47 ; -137.8,-399.61 -137.8,-399.47 ; v2(375,-900) cw(c362.17,-887.17) 362.17,-905.31 261.25,-905.31 cw(c261.25,-834.91) 211.47,-884.69 -88.82,-584.41 cw(c-18.11,-513.7) -118.11,-513.7 -118.11,-446.99 ccw(c-151.71,-446.99) -127.95,-423.23 cw(c-104.19,-399.47) -137.8,-399.47
CLOCK.AIN: U50.D16 U67.7 | length 1004.6
  Top Layer w5: v6(-196.85,-354.33) -196.85,-334.65 cw(c-149.33,-334.65) -182.93,-301.04 U50.D16@-177.17,-295.28 ; v2(375,-925) ccw(c387.83,-912.17) 387.83,-930.31 U67.7@431.79,-930.31
  Int6 (SB) w5: v6(-196.85,-354.33) -191.08,-360.1 cw(c-224.69,-393.7) -177.17,-393.7 -177.17,-399.47 ccw(c-143.56,-399.47) -167.32,-423.23 cw(c-191.08,-446.99) -157.48,-446.99 -157.48,-485.86 ccw(c-18.11,-485.86) -116.66,-584.41 197.55,-898.61 ccw(c261.25,-834.91) 261.25,-925 v2(375,-925)
CLOCK.CNTROUT_N: U50.D1 U56.4 | length 967.2
  Top Layer w4: U56.4@-115.65,-737.6 -79.69,-737.6 ccw(c-79.69,-724.41) -66.5,-724.41 -66.5,-704.72 cw(c-27,-704.72) -27,-665.23 58.78,-665.23 ccw(c58.78,-606.02) 100.64,-647.89 cw(c153.52,-700.76) 153.52,-625.98 295.56,-625.98 ccw(c295.56,-453.05) 468.5,-453.05 468.5,-315.02 ccw(c433.07,-315.02) 433.07,-279.59 423.23,-279.59 ccw(c423.23,-286.93) 415.89,-286.93 415.89,-289.24 cw(c407.35,-289.24) U50.D1@413.39,-295.28
CLOCK.CNTROUT_P: U50.E1 U56.3 | length 979.7
  Top Layer w4: U56.3@-9.35,-737.6 -45.31,-737.6 cw(c-45.31,-724.41) -58.5,-724.41 -58.5,-704.72 cw(c-27,-704.72) -27,-673.23 58.78,-673.23 ccw(c58.78,-606.02) 106.3,-653.54 cw(c153.52,-700.76) 153.52,-633.98 295.56,-633.98 ccw(c295.56,-453.05) 476.5,-453.05 476.5,-315.02 ccw(c433.07,-315.02) 433.07,-271.59 423.23,-271.59 cw(c423.23,-264.25) 415.89,-264.25 415.89,-261.94 ccw(c407.35,-261.94) U50.E1@413.39,-255.91
CLOCK.OSCCLK_N: R164.1 U50.G4 U52.7 | length 1336.2
  Top Layer w4: R164.1@-312.5,-818.16 ccw(c-312.5,-803.94) -298.28,-803.94 -298.28,-765.6 ; U50.G4@295.28,-177.17 ccw(c289.24,-171.13) 297.78,-171.13 297.78,-166.85 cw(c303.15,-166.85) 303.15,-161.48 cw(c303.15,-169.35) 311.02,-169.35 311.02,-177.29 ccw(c334.65,-177.29) 334.65,-200.91 374.14,-200.91 cw(c374.14,-216.54) 389.76,-216.54 389.76,-452.22 cw(c255.5,-452.22) 255.5,-586.49 140.01,-586.49 ccw(c140.01,-667.57) 82.68,-610.24 cw(c44.96,-572.52) 44.96,-625.86 -60.41,-625.86 ccw(c-60.41,-687.63) -104.08,-643.95 cw(c-155.76,-592.27) -155.76,-665.35 -237.8,-665.35 ccw(c-237.8,-725.84) -298.28,-725.84 -298.28,-749.06 ; U52.7@-306.55,-757.33 ccw(c-306.55,-749.06) -298.28,-749.06 ; U52.7@-306.55,-757.33 cw(c-306.55,-765.6) -298.28,-765.6 ; U52.7@-306.55,-757.33 ccw(c-306.55,-749.06) -298.28,-749.06 ; -298.28,-765.6 -298.28,-749.06
CLOCK.OSCCLK_P: R166.2 U50.H4 U52.6 | length 1334.9
  Top Layer w4: U52.6@-289.22,-749.05 U52.6@-289.22,-749.59 ; R166.2@-275,-818.16 cw(c-275,-803.94) -289.22,-803.94 U52.6@-289.22,-749.59 ; U50.H4@295.28,-137.8 cw(c289.24,-143.83) 297.78,-143.83 297.78,-148.11 ccw(c303.15,-148.11) 303.15,-153.48 cw(c303.15,-169.35) 319.02,-169.35 319.02,-177.29 ccw(c334.65,-177.29) 334.65,-192.91 374.14,-192.91 cw(c374.14,-216.54) 397.76,-216.54 397.76,-452.22 cw(c255.5,-452.22) 255.5,-594.49 140.01,-594.49 ccw(c140.01,-667.57) 88.33,-615.89 cw(c44.96,-572.52) 44.96,-633.86 -60.41,-633.86 ccw(c-60.41,-687.63) -98.43,-649.61 cw(c-155.76,-592.27) -155.76,-673.35 -236.76,-673.35 ccw(c-236.76,-725.84) -289.24,-725.84 -289.24,-749.05 ; -289.24,-749.05 ccw(c-280.95,-749.05) U52.6@-289.22,-749.59 ; -289.24,-749.05 ccw(c-280.95,-749.05) U52.6@-289.22,-749.59 ; U52.6@-289.22,-749.59 ccw(c-280.95,-749.05) U52.6@-280.95,-757.33 cw(c-280.95,-749.05) U52.6@-289.22,-749.59
CLOCK.SYNC_N: U50.F1 U61.4 | length 931.5
  Top Layer w4: U61.4@96.85,-737.6 cw(c102.89,-743.63) 102.89,-735.1 123.5,-735.1 ccw(c123.5,-712.6) 146,-712.6 cw(c193.37,-712.6) 193.37,-665.23 315.23,-665.23 ccw(c315.23,-452.9) 527.56,-452.9 527.56,-286.87 ccw(c441.54,-286.87) 441.54,-200.85 425.54,-200.85 ccw(c425.54,-210.5) 415.89,-210.5 cw(c407.35,-210.5) U50.F1@413.39,-216.54
CLOCK.SYNC_P: U50.G1 U61.3 | length 944
  Top Layer w4: U61.3@203.15,-737.6 ccw(c197.11,-743.63) 197.11,-735.1 176.5,-735.1 cw(c176.5,-712.6) 154,-712.6 cw(c193.37,-712.6) 193.37,-673.23 315.23,-673.23 ccw(c315.23,-452.9) 535.56,-452.9 535.56,-286.87 ccw(c441.54,-286.87) 441.54,-192.85 425.54,-192.85 cw(c425.54,-183.2) 415.89,-183.2 ccw(c407.35,-183.2) U50.G1@413.39,-177.17
DONE: Q1.1 R191.1 U50.G11 | length 1096.1
  Top Layer w4.2: U50.G11@19.69,-177.17 v3(39.37,-196.85)
  Top Layer w10: R191.1@785,-440.59 v2(785,-481.79) Q1.1@822.6,-481.79
  Bottom Layer w4.2: v3(39.37,-196.85) 45.14,-191.08 cw(c78.74,-224.69) 78.74,-177.17 629.14,-177.17 cw(c629.14,-333.03) 785,-333.03 v2(785,-481.79)
DVDD1V8: C304A.1 C304B.1 C304C.1 C304D.1 C304E.1 C304F.1 C304G.1 C304H.1 C320A.1 C320B.1 C320C.1 C320D.1 C320E.1 C320F.1 C320G.1 C320H.1 C344A.1 C344B.1 C344C.1 C344D.1 C344E.1 C344F.1 C344G.1 C344H.1 R221.1 R348.2 R349.1 TP20.1 U34A.20 U34A.23 U34B.20 U34B.23 U34C.20 U34C.23 U34D.20 U34D.23 U34E.20 U34E.23 U34F.20 U34F.23 U34G.20 U34G.23 U34H.20 U34H.23 | length 1593.6
  Top Layer w10: U34H.23@-1854.53,-1345.38 v1(-1854.53,-1314.57) ; U34G.23@-1854.53,-895.38 v1(-1854.53,-864.57) ; U34F.23@-1854.53,-445.38 v1(-1854.53,-414.57) ; U34E.23@-1854.53,4.62 v1(-1854.53,35.43) ; U34D.23@-1854.53,454.62 v1(-1854.53,485.43) ; U34C.23@-1854.53,904.62 v1(-1854.53,935.43) ; U34B.23@-1854.53,1354.62 v1(-1854.53,1385.43) ; U34A.23@-1854.53,1804.62 v1(-1854.53,1835.43) ; U34H.20@-1795.47,-1345.38 v1(-1795.47,-1314.57) ; U34G.20@-1795.47,-895.38 v1(-1795.47,-864.57) ; U34F.20@-1795.47,-445.38 v1(-1795.47,-414.57) ; U34E.20@-1795.47,4.62 v1(-1795.47,35.43) ; U34D.20@-1795.47,454.62 v1(-1795.47,485.43) ; U34C.20@-1795.47,904.62 v1(-1795.47,935.43) ; U34B.20@-1795.47,1354.62 v1(-1795.47,1385.43) ; U34A.20@-1795.47,1804.62 v1(-1795.47,1835.43)
  Top Layer w20: TP20.1@1350,-312.5 1358.21,-304.29 cw(c1428.92,-375) 1428.92,-275 R221.1@1674.41,-275
  Bottom Layer w10: v1(-2000,-1712.5) C344H.1@-1968.7,-1712.5 ; v1(-2000,-1262.5) C344G.1@-1968.7,-1262.5 ; v1(-2000,-812.5) C344F.1@-1968.7,-812.5 ; v1(-2000,-362.5) C344E.1@-1968.7,-362.5 ; v1(-2000,87.5) C344D.1@-1968.7,87.5 ; v1(-2000,537.5) C344C.1@-1968.7,537.5 ; v1(-2000,987.5) C344B.1@-1968.7,987.5 ; v1(-2000,1437.5) C344A.1@-1968.7,1437.5 ; C320H.1@-1795.47,-1333.44 v1(-1795.47,-1314.57) ; C320G.1@-1795.47,-883.44 v1(-1795.47,-864.57) ; C320F.1@-1795.47,-433.44 v1(-1795.47,-414.57) ; C320E.1@-1795.47,16.56 v1(-1795.47,35.43) ; C320D.1@-1795.47,466.56 v1(-1795.47,485.43) ; C320C.1@-1795.47,916.56 v1(-1795.47,935.43) ; C320B.1@-1795.47,1366.56 v1(-1795.47,1385.43) ; C320A.1@-1795.47,1816.56 v1(-1795.47,1835.43) ; C304H.1@-1681.3,-1712.5 cw(c-1662.6,-1731.19) -1662.6,-1704.76 v1(-1657.68,-1704.76) ; C304G.1@-1681.3,-1262.5 cw(c-1662.6,-1281.19) -1662.6,-1254.76 v1(-1657.68,-1254.76) ; C304F.1@-1681.3,-812.5 cw(c-1662.6,-831.19) -1662.6,-804.76 v1(-1657.68,-804.76) ; C304E.1@-1681.3,-362.5 cw(c-1662.6,-381.19) -1662.6,-354.76 v1(-1657.68,-354.76) ; C304D.1@-1681.3,87.5 cw(c-1662.6,68.81) -1662.6,95.24 v1(-1657.68,95.24) ; C304C.1@-1681.3,537.5 cw(c-1662.6,518.81) -1662.6,545.24 v1(-1657.68,545.24) ; C304B.1@-1681.3,987.5 cw(c-1662.6,968.81) -1662.6,995.24 v1(-1657.68,995.24) ; C304A.1@-1681.3,1437.5 cw(c-1662.6,1418.81) -1662.6,1445.24 v1(-1657.68,1445.24)
  Bottom Layer w20: R348.2@1350,-391.54 TP20.1@1350,-312.5 R349.1@1350,-233.46
DVDD5V0: C135.2 C312A.1 C312B.1 C312C.1 C312D.1 C312E.1 C312F.1 C312G.1 C312H.1 C328A.1 C328B.1 C328C.1 C328D.1 C328E.1 C328F.1 C328G.1 C328H.1 C336A.1 C336B.1 C336C.1 C336D.1 C336E.1 C336F.1 C336G.1 C336H.1 FR1.2 FR8.2 R319.1 TP23.1 U34A.25 U34B.25 U34C.25 U34D.25 U34E.25 U34F.25 U34G.25 U34H.25 U90.10 U90.11 U90.12 | length 2806.7
  Top Layer w10: U34H.25@-1893.9,-1345.38 v1(-1893.9,-1314.57) ; U34G.25@-1893.9,-895.38 v1(-1893.9,-864.57) ; U34F.25@-1893.9,-445.38 v1(-1893.9,-414.57) ; U34E.25@-1893.9,4.62 v1(-1893.9,35.43) ; U34D.25@-1893.9,454.62 v1(-1893.9,485.43) ; U34C.25@-1893.9,904.62 v1(-1893.9,935.43) ; U34B.25@-1893.9,1354.62 v1(-1893.9,1385.43) ; U34A.25@-1893.9,1804.62 v1(-1893.9,1835.43)
  Top Layer w15: R319.1@1950,599.41 ccw(c2000.3,599.41) 2000.3,549.11 v9(2037.5,549.11) U90.11@2079.44,549.11 ; U90.12@2079.44,523.52 U90.11@2079.44,549.11 ; U90.10@2079.44,574.7 U90.11@2079.44,549.11
  Top Layer w20: v2(356.25,-1325) FR1.2@356.25,-1280.12
  Int5 (ST) w40: TP23.1@1350,587.5 v9(2037.5,549.11)
  Bottom Layer w10: v1(-1893.9,-1314.57) C336H.1@-1893.9,-1333.44 C328H.1@-1874.21,-1333.44 ; v1(-1893.9,-864.57) C336G.1@-1893.9,-883.44 C328G.1@-1874.21,-883.44 ; v1(-1893.9,-414.57) C336F.1@-1893.9,-433.44 C328F.1@-1874.21,-433.44 ; v1(-1893.9,35.43) C336E.1@-1893.9,16.56 C328E.1@-1874.21,16.56 ; v1(-1893.9,485.43) C336D.1@-1893.9,466.56 C328D.1@-1874.21,466.56 ; v1(-1893.9,935.43) C336C.1@-1893.9,916.56 C328C.1@-1874.21,916.56 ; v1(-1893.9,1385.43) C336B.1@-1893.9,1366.56 C328B.1@-1874.21,1366.56 ; v1(-1893.9,1835.43) C336A.1@-1893.9,1816.56 C328A.1@-1874.21,1816.56 ; v1(-1875,-1705) -1868.7,-1705 cw(c-1868.7,-1730.61) C312H.1@-1850.59,-1712.5 ; v1(-1875,-1255) -1868.7,-1255 cw(c-1868.7,-1280.61) C312G.1@-1850.59,-1262.5 ; v1(-1875,-805) -1868.7,-805 cw(c-1868.7,-830.61) C312F.1@-1850.59,-812.5 ; v1(-1875,-355) -1868.7,-355 cw(c-1868.7,-380.61) C312E.1@-1850.59,-362.5 ; v1(-1875,95) -1868.7,95 cw(c-1868.7,69.39) C312D.1@-1850.59,87.5 ; v1(-1875,545) -1868.7,545 cw(c-1868.7,519.39) C312C.1@-1850.59,537.5 ; v1(-1875,995) -1868.7,995 cw(c-1868.7,969.39) C312B.1@-1850.59,987.5 ; v1(-1875,1445) -1868.7,1445 cw(c-1868.7,1419.39) C312A.1@-1850.59,1437.5
  Bottom Layer w50: FR8.2@575,794.88 585.43,788.39 TP23.1@1350,587.5 C135.2@1644.88,587.5
DVDDL1V8: C130.2 R348.1 U85.10 U85.11 U85.12 | length 1149.2
  Top Layer w15: U85.12@2079.44,-476.48 2074.28,-476.48 cw(c2074.28,-389.1) v8(2012.5,-450.89) ; U85.11@2079.44,-450.89 v8(2012.5,-450.89) ; U85.10@2079.44,-425.3 2074.28,-425.3 ccw(c2074.28,-512.67) v8(2012.5,-450.89)
  Int5 (ST) w40: v8(1387.5,-458.46) v8(2012.5,-450.89)
  Bottom Layer w35: R348.1@1350,-458.46 v8(1387.5,-458.46) 1557.5,-458.46 ccw(c1557.5,-358.46) 1628.21,-429.18 C130.2@1644.88,-412.5
DVDDR1V8: C131.2 R349.2 U86.10 U86.11 U86.12 | length 1154.8
  Top Layer w15: U86.12@2079.44,-276.48 2074.28,-276.48 cw(c2074.28,-189.1) v8(2012.5,-250.89) ; U86.11@2079.44,-250.89 v8(2012.5,-250.89) ; U86.10@2079.44,-225.3 2074.28,-225.3 ccw(c2074.28,-312.67) v8(2012.5,-250.89)
  Int5 (ST) w40: v8(1387.5,-166.54) v8(2012.5,-250.89)
  Bottom Layer w35: R349.2@1350,-166.54 v8(1387.5,-166.54) 1557.5,-166.54 cw(c1557.5,-266.54) 1628.21,-195.82 C131.2@1644.88,-212.5
EMCLK_EN: R145.2 U50.U21 Y1.1 | length 768.9
  Top Layer w5: U50.U21@-374.02,216.54 v3(-354.33,196.85)
  Top Layer w10: R145.2@-825,549.41 ccw(c-813.12,561.29) -813.12,544.49 v1(-794.18,544.49) Y1.1@-769.98,544.49
  Int6 (SB) w5: v1(-794.18,544.49) -721.89,472.2 ccw(c-651.18,542.91) -651.18,442.91 -452.76,442.91 cw(c-452.76,403.54) -413.39,403.54 -413.39,236.22 ccw(c-393.7,236.22) -393.7,216.54 cw(c-393.7,169.01) -360.09,202.62 v3(-354.33,196.85)
EXT12V: J2.1 J2.2 J2.3 R296.1 | length 1074.2
  Bottom Layer w50: 2387.5,1507.5 2387.5,1400 ccw(c2487.5,1400) 2487.5,1300 2762.5,1300 ccw(c2762.5,1400) 2862.5,1400 J2.3@2862.5,1446.79 J2.2@2862.5,1612.5 J2.1@2862.5,1777.5
EXT.TRIGout_N: R148.1 R382.1 U48.2 U50.H5 | length 1093
  Top Layer w5: v16(-683.07,-214.19) R148.1@-683.07,-226.38 cw(c-676.18,-226.38) -676.18,-219.49 U48.2@-621.85,-219.49 ; U50.H5@255.91,-137.8 v6(275.59,-157.48)
  Bottom Layer w4: v16(-683.07,-214.19) cw(c-674.62,-222.64) -674.62,-210.69 -511.81,-210.69 ccw(c-511.81,-169.27) -482.52,-198.56 -476.63,-192.66 cw(c-449.02,-220.27) -449.02,-181.23 -432.54,-181.23 ccw(c-432.54,-112.74) -384.11,-161.17 cw(c-337.34,-207.94) -337.34,-141.8 259.91,-141.8 cw(c259.91,-157.48) v6(275.59,-157.48)
EXT.TRIGout_P: R149.1 R382.2 U48.3 U50.J5 | length 1093
  Top Layer w5: v16(-683.07,-199.19) R149.1@-683.07,-187.01 ccw(c-676.18,-187.01) -676.18,-193.9 U48.3@-621.85,-193.9 ; U50.J5@255.91,-98.43 v6(275.59,-118.11)
  Bottom Layer w4: v16(-683.07,-199.19) ccw(c-674.62,-190.74) -674.62,-202.69 -511.81,-202.69 ccw(c-511.81,-169.27) -488.18,-192.9 -482.28,-187.01 cw(c-449.02,-220.27) -449.02,-173.23 -432.54,-173.23 ccw(c-432.54,-112.74) -389.76,-155.51 cw(c-337.34,-207.94) -337.34,-133.8 259.91,-133.8 ccw(c259.91,-118.11) v6(275.59,-118.11)
EXTCLK.CAUX_N: R188.2 U50.T4 U70.6 | length 1481.3
  Top Layer w4: U50.T4@295.28,177.17 ccw(c310.96,177.17) 310.96,161.48 452.82,161.48 ccw(c452.82,177.17) 468.5,177.17 468.5,375.94 cw(c545.86,375.94) 491.16,430.64 ; 491.18,430.66 ccw(c446.95,474.89) 509.5,474.89 509.5,530.15 cw(c617.4,530.15) 541.1,606.44 721.15,786.49 ccw(c661.17,846.48) 746,846.48 746,1265.02 ccw(c736,1265.02) 743.07,1272.09 742.97,1272.09 740.09,1274.97 cw(c747.05,1281.93) 737.2,1281.93 U70.6@737.2,1301.08 737.2,1344.52 ccw(c712.61,1344.52) R188.2@730,1361.91
EXTCLK.CAUX_P: R190.2 U50.R4 U70.7 | length 1492.6
  Top Layer w4: U50.R4@295.28,137.8 cw(c310.96,137.8) 310.96,153.48 452.82,153.48 ccw(c452.82,177.17) 476.5,177.17 476.5,375.91 cw(c545.92,375.91) 496.84,425 ccw(c447.01,474.86) 517.5,474.86 517.5,530.1 cw(c617.5,530.1) 546.79,600.82 726.89,780.92 ccw(c661.44,846.37) 754,846.37 754,1265.02 cw(c764,1265.02) 756.93,1272.09 757.03,1272.09 U70.7@759.91,1274.97 ; U70.7@759.92,1274.98 ccw(c752.95,1281.93) 762.8,1281.93 U70.7@762.8,1301.08 762.8,1343.27 cw(c787.39,1343.27) R190.2@770,1360.66
EXTGND: FL1.3 FL2.3 J2.4 J2.5 J2.6 P2.A4 P2.A12 P2.A15 P2.A18 P2.A20 P2.A23 P2.A24 P2.A27 P2.A28 P2.A31 P2.B4 P2.B7 P2.B13 P2.B16 P2.B18 P2.B21 P2.B22 P2.B25 P2.B26 P2.B29 P2.B32 TP32.1 | length 2971.9
  Top Layer w17.91: P2.B4@-1684.65,-2385 v2(-1684.65,-2250) ; P2.B7@-1566.54,-2385 -1566.54,-2271.17 cw(c-1545.36,-2271.17) v2(-1545.36,-2250) ; v2(-1270,-2250) cw(c-1270,-2268.43) -1251.57,-2268.43 P2.B13@-1251.57,-2385 ; v2(-1152.5,-2250) cw(c-1152.5,-2269.04) -1133.46,-2269.04 P2.B16@-1133.46,-2385 ; P2.B18@-1054.72,-2385 v2(-1054.72,-2250) ; v2(-955,-2250) cw(c-955,-2268.38) -936.61,-2268.38 P2.B21@-936.61,-2385 ; P2.B22@-897.24,-2385 -897.24,-2269.74 cw(c-877.5,-2269.74) v2(-877.5,-2250) ; v2(-797.5,-2250) cw(c-797.5,-2268.37) -779.13,-2268.37 P2.B25@-779.13,-2385 ; P2.B26@-739.76,-2385 -739.76,-2269.76 cw(c-720,-2269.76) v2(-720,-2250) ; v2(-642.5,-2250) cw(c-642.5,-2270.85) -621.65,-2270.85 P2.B29@-621.65,-2385 ; v2(-522.5,-2250) cw(c-522.5,-2268.96) -503.54,-2268.96 P2.B32@-503.54,-2385
  Bottom Layer w17.91: P2.A4@-1684.65,-2385 v2(-1684.65,-2250) ; P2.A12@-1290.94,-2330.02 -1290.94,-2270.94 cw(c-1270,-2270.94) v2(-1270,-2250) ; P2.A15@-1172.83,-2385 -1172.83,-2270.33 cw(c-1152.5,-2270.33) v2(-1152.5,-2250) ; P2.A18@-1054.72,-2385 v2(-1054.72,-2250) ; P2.A20@-975.99,-2385 -975.99,-2270.99 cw(c-955,-2270.99) v2(-955,-2250) ; v2(-877.5,-2250) cw(c-877.5,-2269.63) -857.87,-2269.63 P2.A23@-857.87,-2385 ; P2.A24@-818.5,-2385 -818.5,-2271 cw(c-797.5,-2271) v2(-797.5,-2250) ; v2(-720,-2250) cw(c-720,-2269.61) -700.39,-2269.61 P2.A27@-700.39,-2385 ; P2.A28@-661.02,-2385 -661.02,-2268.52 cw(c-642.5,-2268.52) v2(-642.5,-2250) ; P2.A31@-542.91,-2385 -542.91,-2270.41 cw(c-522.5,-2270.41) v2(-522.5,-2250)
